Omron Sysmac Studio project sample_eip_test_4 (Sysmac Studio 1.30.0.17, StandardProject)

# Controller new_Controller_0: NX102-9000 version 1.31
Task PrimaryTask (priority 4, period or condition 2000): Program0

VAR_GLOBAL RETAIN
    DataIn AT %D100 : ARRAY[0..199] OF BYTE;  (* network input *)
    DataOut AT %D0 : ARRAY[0..199] OF BYTE;  (* network output *)
END_VAR

PROGRAM Program0
VAR RETAIN
    TriggerEnable AT %D0.0 : BOOL;
    Trigger AT %D0.1 : BOOL;
    ResultsAck AT %D0.2 : BOOL;
    ClearError AT %D0.15 : BOOL;
    TriggerReady AT %D101.0 : BOOL;
    TriggerAck AT %D101.1 : BOOL;
    Acquiring AT %D101.2 : BOOL;
    Decoding AT %D101.3 : BOOL;
    ResultsOK AT %D101.8 : BOOL;
    ResultsNG AT %D101.9 : BOOL;
    GeneralFault AT %D101.15 : BOOL;
    ResultLength AT %D109 : UINT;
    ResultData AT %D110 : ARRAY[0..179] OF BYTE;
    ResultDataUser AT %D500 : ARRAY[0..179] OF BYTE;
END_VAR
VAR
    _p1 : BOOL;
    _e2 : R_TRIG;
    _e3 : F_TRIG;
END_VAR

(* Section Section0: ladder, written here as Structured Text *)

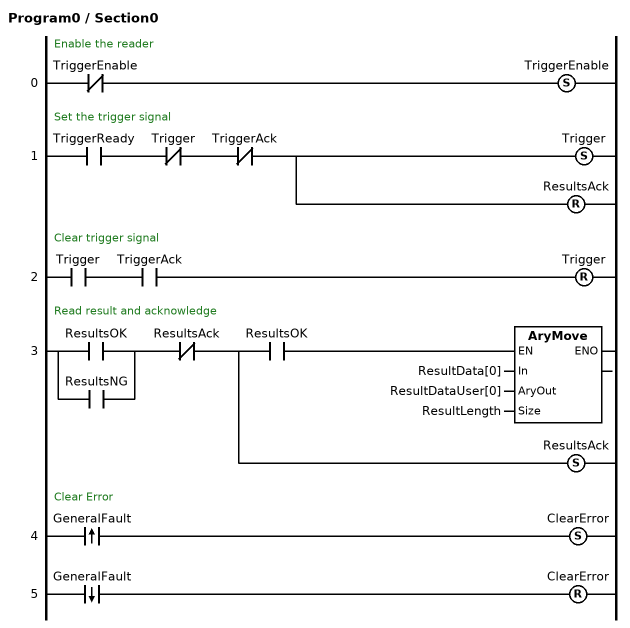
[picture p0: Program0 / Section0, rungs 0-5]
(* Rung 0: Enable the reader *)
IF NOT TriggerEnable THEN TriggerEnable := TRUE; END_IF;
(* Rung 1: Set the trigger signal *)
_p1 := TriggerReady AND NOT Trigger AND NOT TriggerAck;
IF _p1 THEN
    Trigger := TRUE;
    ResultsAck := FALSE;
END_IF;
(* Rung 2: Clear trigger signal *)
IF Trigger AND TriggerAck THEN Trigger := FALSE; END_IF;
(* Rung 3: Read result and acknowledge *)
IF (ResultsOK OR ResultsNG) AND NOT ResultsAck AND ResultsOK THEN
    AryMove(In := ResultData[0], AryOut := ResultDataUser[0], Size := ResultLength);
END_IF;
IF (ResultsOK OR ResultsNG) AND NOT ResultsAck THEN ResultsAck := TRUE; END_IF;
(* Rung 4: Clear Error *)
_e2(CLK := GeneralFault);
IF _e2.Q THEN ClearError := TRUE; END_IF;
(* Rung 5 *)
_e3(CLK := GeneralFault);
IF _e3.Q THEN ClearError := FALSE; END_IF;
END_PROGRAM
